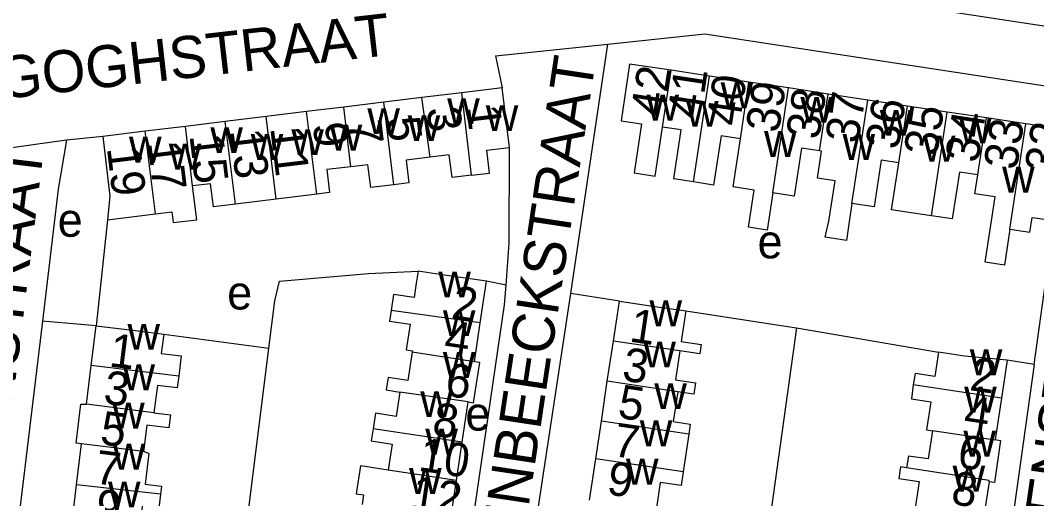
# Model space of a CAD drawing. Extents: x 161775 to 163181, y 382878 to 383925.
# Drawn here: x 162855 to 162975.8, y 383224.4 to 383281.3 of the extents above; entities that cross this region are included whole.
import ezdxf

# ---------------------------------------------------------------- set-up
doc = ezdxf.new("R2010")
doc.units = 0
for name, color, linetype in [('BLT_Basislijn', 7, 'Continuous'), ('BLT_Bebouwing', 7, 'Continuous'), ('BLT_Centroide', 7, 'Continuous'), ('BLT_Huisnummer', 7, 'Continuous'), ('BLT_Huisnummer_ tussenligend', 7, 'Continuous'), ('BLT_Onderverdeling_panden', 7, 'Continuous'), ('BLT_Straatnaam', 7, 'Continuous'), ('BLT_Vlakafsluiter', 7, 'Continuous')]:
    doc.layers.add(name, color=color, linetype=linetype)

msp = doc.modelspace()

# ---------------------------------------------------------------- linework, layer by layer
at = {"layer": 'BLT_Basislijn'}
for p, q in [((162920.4, 383248.77), (162924.82, 383278.44)), ((162911.46, 383277.04), (162912.27, 383273.24)), ((162864.77, 383267.46), (162860.47, 383267)), ((162865.32, 383257.55), (162864, 383244.94)), ((162975.49, 383240.34), (162977.86, 383257.45)), ((162912.71, 383249.77), (162910.37, 383250.25)), ((162913.79, 383205.27), (162920.4, 383248.77)), ((162926.18, 383247.85), (162920.4, 383248.77)), ((162934.07, 383246.71), (162947.24, 383244.69)), ((162864, 383244.94), (162857.59, 383245.49)), ((162872.02, 383243.95), (162884.53, 383242.27)), ((162947.24, 383244.69), (162941.23, 383201.28)), ((162947.24, 383244.69), (162964.12, 383241.82)), ((162880.51, 383210.3), (162884.53, 383242.27)), ((162975.49, 383240.34), (162968.75, 383192.16)), ((162975.49, 383240.34), (162972.27, 383240.84))]:
    msp.add_line(p, q, dxfattribs=at)
for points in [[(162979.98, 383278.38), (162978.77, 383278.55), (162977.68, 383280.41), (162946.45, 383285.2), (162944.13, 383283.65), (162941.19, 383284.27)], [(162924.82, 383278.44), (162936.33, 383279.66), (162979.93, 383273.01)], [(162860.47, 383267), (162859.46, 383261.19), (162857.59, 383245.49)], [(162912.71, 383249.77), (162913.09, 383254.76), (162913.12, 383266.13)], [(162884.53, 383242.27), (162885.24, 383247.9), (162885.77, 383250.23), (162896.37, 383251.17), (162902.27, 383251.44)], [(162906.5, 383205.99), (162906.52, 383206.12), (162912.52, 383247.44), (162912.71, 383249.77)], [(162857.59, 383245.49), (162853.35, 383210.37), (162852.65, 383200.3), (162849.19, 383172.97), (162849.18, 383172.77)]]:
    msp.add_lwpolyline(points, dxfattribs=at)
at = {"layer": 'BLT_Bebouwing'}
for p, q in [((162936.89, 383274.64), (162932.35, 383275.32)), ((162941.59, 383273.93), (162936.89, 383274.64)), ((162912.27, 383273.24), (162907.44, 383272.65)), ((162913.12, 383266.13), (162912.27, 383273.24)), ((162946.3, 383273.22), (162941.59, 383273.93)), ((162950.99, 383272.49), (162946.3, 383273.22)), ((162902.7, 383272.07), (162898.2, 383271.53)), ((162907.44, 383272.65), (162902.7, 383272.07)), ((162955.71, 383271.78), (162950.99, 383272.49)), ((162960.43, 383271.06), (162955.71, 383271.78)), ((162889.01, 383270.41), (162884.19, 383269.82)), ((162893.42, 383270.94), (162889.01, 383270.41)), ((162898.2, 383271.53), (162893.42, 383270.94)), ((162965.16, 383270.34), (162960.43, 383271.06)), ((162879.34, 383269.23), (162874.59, 383268.65)), ((162884.19, 383269.82), (162879.34, 383269.23)), ((162969.81, 383269.68), (162965.16, 383270.34)), ((162974.51, 383268.96), (162969.81, 383269.68)), ((162869.83, 383268.07), (162864.77, 383267.46)), ((162874.59, 383268.65), (162869.83, 383268.07)), ((162979.46, 383268.22), (162974.51, 383268.96)), ((162885.38, 383260.01), (162880.53, 383259.41)), ((162890.2, 383260.6), (162885.38, 383260.01)), ((162909.63, 383245.29), (162910.37, 383250.25)), ((162925.47, 383243.13), (162926.18, 383247.85)), ((162908.95, 383240.67), (162909.63, 383245.29)), ((162863.41, 383240.22), (162864, 383244.94)), ((162924.75, 383238.34), (162925.47, 383243.13)), ((162901.59, 383241.96), (162901.56, 383241.79)), ((162862.84, 383235.6), (162863.41, 383240.22)), ((162972.27, 383240.84), (162971.6, 383236.32)), ((162924.05, 383233.61), (162924.75, 383238.34)), ((162907.5, 383231.1), (162908.22, 383235.88)), ((162971.6, 383236.32), (162970.86, 383231.4)), ((162923.38, 383229.13), (162924.05, 383233.61)), ((162934.43, 383232.05), (162933.76, 383227.57)), ((162861.66, 383226.04), (162862.26, 383230.91)), ((162906.82, 383226.56), (162907.5, 383231.1)), ((162870.25, 383229.75), (162869.62, 383229.99)), ((162922.64, 383224.19), (162923.38, 383229.13)), ((162861.12, 383221.66), (162861.66, 383226.04)), ((162906.15, 383222.1), (162906.82, 383226.56)), ((162970.14, 383226.4), (162969.52, 383222.31))]:
    msp.add_line(p, q, dxfattribs=at)
for points in [[(162932.35, 383275.32), (162927.4, 383276.07), (162926.38, 383269.33)], [(162926.38, 383269.33), (162928.83, 383268.94), (162927.95, 383263.13), (162930.45, 383262.75), (162931.33, 383268.57)], [(162934.99, 383262.05), (162932.66, 383262.4), (162933.54, 383268.24), (162931.33, 383268.57)], [(162864.77, 383267.46), (162865.62, 383260.35), (162865.32, 383257.55)], [(162940.57, 383267.17), (162938.28, 383267.52), (162937.39, 383261.68), (162934.99, 383262.05)], [(162944.41, 383260.74), (162943.74, 383256.32), (162941.52, 383256.66), (162942.19, 383261.07), (162939.71, 383261.45), (162940.57, 383267.17)], [(162908.62, 383262.85), (162910.76, 383263.11), (162910.43, 383265.81), (162913.12, 383266.13)], [(162949.96, 383265.75), (162947.84, 383266.07), (162946.97, 383260.35), (162944.41, 383260.74)], [(162953.83, 383259.47), (162953.46, 383257.02), (162953.17, 383255.08), (162950.63, 383255.47), (162951.09, 383257.38), (162951.82, 383262.16), (162949.73, 383262.48), (162950.22, 383265.71), (162949.96, 383265.75)], [(162903.68, 383264.99), (162900.83, 383264.65), (162901.16, 383261.94), (162899.39, 383261.72)], [(162908.62, 383262.85), (162906.32, 383262.57), (162905.96, 383265.27), (162903.68, 383264.99)], [(162959.41, 383264.31), (162957.31, 383264.63), (162956.46, 383259.07), (162953.83, 383259.47)], [(162894.26, 383263.85), (162891.4, 383263.51), (162891.73, 383260.78), (162890.2, 383260.6)], [(162899.39, 383261.72), (162896.63, 383261.38), (162896.3, 383264.1), (162894.26, 383263.85)], [(162963.28, 383258.01), (162960.89, 383258.38), (162958.53, 383258.73), (162959.41, 383264.31)], [(162968.78, 383262.89), (162966.6, 383263.22), (162965.75, 383257.64), (162963.28, 383258.01)], [(162972.61, 383256.44), (162971.96, 383252.15), (162969.68, 383252.49), (162970.86, 383260.26), (162968.43, 383260.63), (162968.78, 383262.89)], [(162871.02, 383258.24), (162873, 383258.48), (162873.15, 383257.22), (162875.94, 383257.56), (162875.45, 383261.57)], [(162880.53, 383259.41), (162877.93, 383259.08), (162877.59, 383261.83), (162875.45, 383261.57)], [(162865.32, 383257.55), (162871.02, 383258.24)], [(162972.61, 383256.44), (162975, 383256.08), (162975.26, 383257.8), (162977.86, 383257.45)], [(162902.27, 383251.44), (162902.04, 383250), (162901.79, 383248.31), (162899.35, 383248.68), (162899.06, 383246.74)], [(162910.37, 383250.25), (162905.35, 383250.98), (162902.27, 383251.44)], [(162926.18, 383247.85), (162930.95, 383247.17), (162934.07, 383246.71)], [(162899.06, 383246.74), (162898.87, 383245.5), (162901.31, 383245.13), (162900.84, 383242.08), (162901.59, 383241.96)], [(162934.07, 383246.71), (162933.53, 383243.08), (162935.92, 383242.72), (162935.75, 383241.6), (162933.36, 383241.95)], [(162864, 383244.94), (162868.97, 383244.33), (162872.02, 383243.95)], [(162872.02, 383243.95), (162871.73, 383241.64), (162874.09, 383241.35), (162873.8, 383238.96)], [(162901.56, 383241.79), (162901.05, 383238.42), (162898.7, 383238.78), (162898.48, 383237.31), (162900.1, 383237.06)], [(162933.36, 383241.95), (162932.86, 383238.51), (162935.24, 383238.16), (162935.04, 383236.82), (162933.12, 383237.1)], [(162964.12, 383241.82), (162963.67, 383238.92), (162961.35, 383239.27), (162961.12, 383237.9)], [(162972.27, 383240.84), (162967.2, 383241.34), (162964.12, 383241.82)], [(162908.22, 383235.88), (162908.86, 383235.78), (162909.6, 383240.57), (162908.95, 383240.67)], [(162873.8, 383238.96), (162873.62, 383237.55), (162871.26, 383237.85), (162870.86, 383234.6)], [(162961.12, 383237.9), (162960.9, 383236.26), (162963.21, 383235.91), (162962.7, 383232.56), (162963.42, 383232.45)], [(162900.1, 383237.06), (162899.66, 383234.16), (162897.18, 383234.53), (162896.9, 383232.7)], [(162933.12, 383237.1), (162932.59, 383233.55), (162934.61, 383233.24), (162934.43, 383232.05)], [(162862.26, 383230.91), (162861.6, 383230.99), (162862.17, 383235.6), (162862.84, 383235.6)], [(162870.86, 383234.6), (162872.83, 383234.36), (162872.63, 383232.8), (162870.01, 383233.13), (162869.62, 383229.99)], [(162896.9, 383232.7), (162896.68, 383231.25), (162899.17, 383230.87), (162898.7, 383227.78)], [(162963.42, 383232.45), (162962.91, 383229.1), (162960.54, 383229.45), (162960.33, 383228.05)], [(162970.86, 383231.4), (162971.5, 383231.31), (162970.78, 383226.3), (162970.14, 383226.4)], [(162870.25, 383229.75), (162869.8, 383226.12), (162871.76, 383225.88), (162871.65, 383224.91)], [(162898.7, 383227.78), (162895.41, 383228.28), (162894.91, 383224.97), (162895.78, 383224.84), (162895.61, 383223.69)], [(162960.33, 383228.05), (162959.62, 383228.15), (162959.41, 383226.78), (162961.82, 383226.42), (162961.38, 383223.53)], [(162933.76, 383227.57), (162933.52, 383225.94), (162931.05, 383226.31), (162930.56, 383223.01)], [(162871.65, 383224.91), (162871.43, 383223.21), (162869.47, 383223.46), (162869.12, 383220.67)]]:
    msp.add_lwpolyline(points, dxfattribs=at)
at = {"layer": 'BLT_Onderverdeling_panden'}
for p, q in [((162931.33, 383268.57), (162932.35, 383275.32)), ((162934.99, 383262.05), (162936.89, 383274.64)), ((162940.57, 383267.17), (162941.59, 383273.93)), ((162944.41, 383260.74), (162946.3, 383273.22)), ((162903.68, 383264.99), (162902.7, 383272.07)), ((162908.62, 383262.85), (162907.44, 383272.65)), ((162949.96, 383265.75), (162950.99, 383272.49)), ((162953.83, 383259.47), (162955.71, 383271.78)), ((162890.2, 383260.6), (162889.01, 383270.41)), ((162894.26, 383263.85), (162893.42, 383270.94)), ((162899.39, 383261.72), (162898.2, 383271.53)), ((162959.41, 383264.31), (162960.43, 383271.06)), ((162880.53, 383259.41), (162879.34, 383269.23)), ((162885.38, 383260.01), (162884.19, 383269.82)), ((162963.28, 383258.01), (162965.16, 383270.34)), ((162968.78, 383262.89), (162969.81, 383269.68)), ((162871.02, 383258.24), (162869.83, 383268.07)), ((162875.45, 383261.57), (162874.59, 383268.65)), ((162972.61, 383256.44), (162974.51, 383268.96)), ((162909.63, 383245.29), (162899.06, 383246.74)), ((162933.36, 383241.95), (162925.47, 383243.13)), ((162908.95, 383240.67), (162901.56, 383241.79)), ((162873.8, 383238.96), (162863.41, 383240.22)), ((162933.12, 383237.1), (162924.75, 383238.34)), ((162908.22, 383235.88), (162900.1, 383237.06)), ((162870.86, 383234.6), (162862.84, 383235.6)), ((162934.43, 383232.05), (162924.05, 383233.61)), ((162907.5, 383231.1), (162896.9, 383232.7)), ((162869.62, 383229.99), (162862.26, 383230.91)), ((162933.76, 383227.57), (162923.38, 383229.13)), ((162906.82, 383226.56), (162898.7, 383227.78)), ((162871.65, 383224.91), (162861.66, 383226.04))]:
    msp.add_line(p, q, dxfattribs=at)
for points in [[(162971.6, 383236.32), (162961.12, 383237.9)], [(162970.86, 383231.4), (162970.85, 383231.33), (162963.42, 383232.45)], [(162970.14, 383226.4), (162970.16, 383226.56), (162960.33, 383228.05)]]:
    msp.add_lwpolyline(points, dxfattribs=at)
at = {"layer": 'BLT_Vlakafsluiter'}
for p, q in [((162911.46, 383277.04), (162924.82, 383278.44)), ((162860.47, 383267), (162850.08, 383265.57))]:
    msp.add_line(p, q, dxfattribs=at)

# ---------------------------------------------------------------- texts
at = {"layer": 'BLT_Centroide'}
for s, p in [('w', (162938.22, 383270.81)), ('w', (162905.72, 383268.92)), ('w', (162929.41, 383269.34)), ('w', (162934.12, 383268.62)), ('w', (162947.7, 383269.09)), ('w', (162896.23, 383267.73)), ('w', (162910.3, 383268.09)), ('w', (162957.14, 383267.55)), ('w', (162901.02, 383266.91)), ('w', (162966.58, 383266.62)), ('w', (162877.56, 383265.47)), ('w', (162887.19, 383265.25)), ('w', (162891.75, 383265.78)), ('w', (162943.39, 383265.02)), ('w', (162867.89, 383264.34)), ('w', (162882.36, 383264.66)), ('w', (162952.72, 383264.67)), ('w', (162962.28, 383264.47)), ('w', (162872.62, 383263.52)), ('w', (162971.69, 383260.78)), ('e', (162859.41, 383255.53)), ('e', (162942.61, 383252.96)), ('w', (162904.66, 383248.31)), ('e', (162879.56, 383246.88)), ('w', (162929.77, 383244.88)), ('w', (162905.21, 383243.72)), ('w', (162867.71, 383242.09)), ('w', (162929.04, 383240)), ('w', (162905.2, 383238.75)), ('w', (162967.85, 383239.06)), ('w', (162867.12, 383237.28)), ('w', (162930.34, 383235.03)), ('w', (162902.51, 383234.09)), ('w', (162967.18, 383234.62)), ('w', (162865.89, 383232.72)), ('e', (162907.88, 383232.48)), ('w', (162928.61, 383230.62)), ('w', (162903.12, 383229.62)), ('w', (162967.09, 383229.38)), ('w', (162865.95, 383227.84)), ('w', (162926.97, 383226.06)), ('w', (162965.8, 383225.22)), ('w', (162901.19, 383224.94)), ('w', (162865.39, 383223.34))]:
    msp.add_text(s, height=4, dxfattribs=at).set_placement(p)
at = {"layer": 'BLT_Huisnummer'}
for s, rotation, p in [('42', 81.3624, (162931.45, 383269.64)), ('40', 81.3637, (162940.45, 383268.57)), ('38', 81.365, (162949.92, 383266.99)), ('36', 81.3579, (162959.36, 383265.8)), ('1', 276.9002, (162907.98, 383271.01)), ('5', 276.9011, (162898.47, 383269.62)), ('34', 81.3611, (162968.85, 383264.22)), ('13', 276.9011, (162879.88, 383268.16)), ('9', 276.9011, (162889.72, 383268.93)), ('32', 81.2615, (162978.28, 383262.97)), ('17', 276.9011, (162870.09, 383266.72)), ('2', 351.456, (162906.08, 383245.81)), ('1', 351.5865, (162927.26, 383243.08)), ('4', 351.456, (162905.21, 383241.7)), ('2', 351.4734, (162967.71, 383237.3)), ('3', 352.9365, (162864.75, 383235.69)), ('8', 351.457, (162903.8, 383231.93)), ('7', 351.5845, (162925.29, 383229.48)), ('6', 351.4761, (162966.24, 383228.1)), ('7', 352.9339, (162863.7, 383226.21)), ('12', 351.4567, (162901.25, 383223.21))]:
    msp.add_text(s, height=4, rotation=rotation, dxfattribs=at).set_placement(p)
at = {"layer": 'BLT_Huisnummer_ tussenligend'}
for s, rotation, p in [('41', 81.3637, (162935.81, 383269.41)), ('39', 81.365, (162945.13, 383267.78)), ('37', 81.3662, (162954.58, 383266.51)), ('3', 276.9002, (162903.24, 383270.78)), ('35', 81.3592, (162963.92, 383264.99)), ('7', 276.9011, (162893.88, 383269.21)), ('33', 81.3751, (162973.42, 383263.38)), ('11', 276.9011, (162884.67, 383268.47)), ('15', 276.9011, (162875.07, 383267.57)), ('19', 276.9011, (162865.25, 383266.08)), ('1', 352.9365, (162865.41, 383240.11)), ('3', 351.5865, (162926.39, 383238.46)), ('6', 351.457, (162905.33, 383236.65)), ('5', 351.5845, (162925.88, 383234.02)), ('4', 351.4734, (162966.99, 383232.77)), ('5', 352.9339, (162864.35, 383230.86)), ('10', 351.4567, (162902.18, 383227.73)), ('9', 351.5814, (162924.57, 383224.92)), ('8', 351.4761, (162965.49, 383223.77)), ('9', 352.9392, (162863.75, 383221.61))]:
    msp.add_text(s, height=4, rotation=rotation, dxfattribs=at).set_placement(p)
at = {"layer": 'BLT_Straatnaam'}
for s, rotation, p in [('VINCENT VAN GOGHSTRAAT', 6.5128, (162806.13, 383266.55)), ('ABRAHAM VAN DIEPENBEECKSTRAAT', 81.4307, (162904.86, 383153.49)), ('JAN VAN GOYENSTRAAT', 82.9955, (162847.96, 383186.04)), ('THEODOOR VAN THULDENSTRAAT', 81.8335, (162968.23, 383144.45))]:
    msp.add_text(s, height=5, rotation=rotation, dxfattribs=at).set_placement(p)

doc.saveas('drawing.dxf')
